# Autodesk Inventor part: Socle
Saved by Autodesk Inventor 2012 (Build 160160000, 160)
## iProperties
Created: 2013-08
Part Number: Socle
Material: Default
Document SubType Name: Modeling
Designer: hilarion
Density: 1 g/cm^3
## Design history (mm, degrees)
node "Socle1"
node "Socle"
node "Base1"
